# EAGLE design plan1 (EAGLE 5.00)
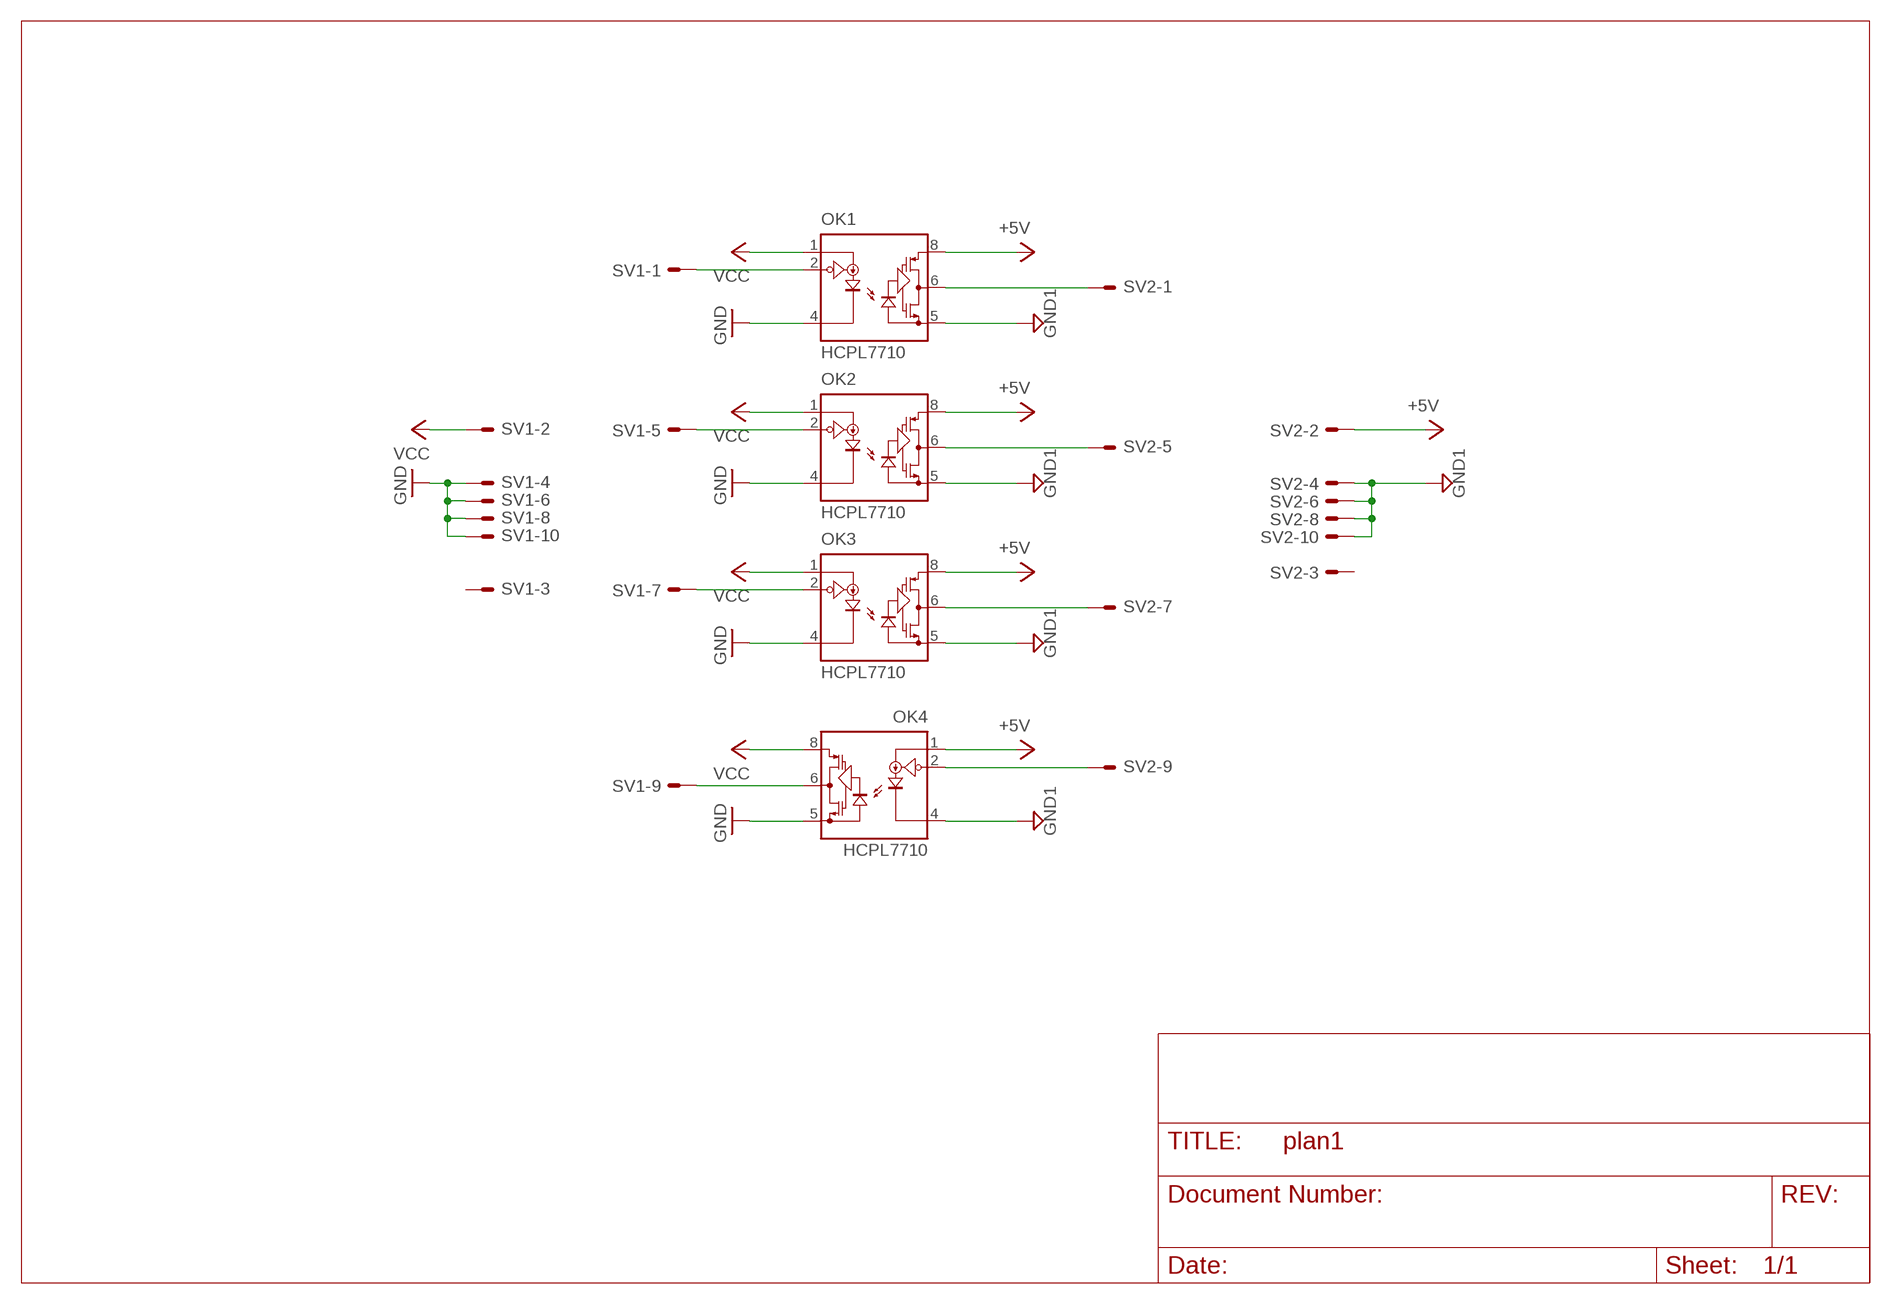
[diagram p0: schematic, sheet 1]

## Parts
OK1  HCPL7710  HCPL7720  [DIL08]
OK2  HCPL7710  HCPL7720  [DIL08]
OK3  HCPL7710  HCPL7720  [DIL08]
OK4  HCPL7710  HCPL7720  [DIL08]
SV1  ML10E  [ML10]
SV2  ML10E  [ML10]

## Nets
+5V: OK1.8(VDD2) OK2.8(VDD2) OK3.8(VDD2) OK4.1(VDD1) SV2.2
GND: OK1.4(GND1) OK2.4(GND1) OK3.4(GND1) OK4.5(GND2) SV1.4 SV1.6 SV1.8 SV1.10
GND1: OK1.5(GND2) OK2.5(GND2) OK3.5(GND2) OK4.4(GND1) SV2.4 SV2.6 SV2.8 SV2.10
N$1: OK1.2(VI) SV1.1
N$2: OK2.2(VI) SV1.5
N$3: OK3.2(VI) SV1.7
N$4: OK4.6(VO) SV1.9
N$5: OK1.6(VO) SV2.1
N$6: OK2.6(VO) SV2.5
N$7: OK3.6(VO) SV2.7
N$8: OK4.2(VI) SV2.9
VCC: OK1.1(VDD1) OK2.1(VDD1) OK3.1(VDD1) OK4.8(VDD2) SV1.2
Unconnected: SV1.3 SV2.3

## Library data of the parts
OK1-OK4 = optocoupler:HCPL772*: 40 ns Propagation Delay, CMOS Optocoupler *Pin 3 is the anode of the internal LED and must be left unconnected for guaranteed data sheet perfomance. Pin 7 is not connected internally. Source: HCPL7721.pdf
SV1 SV2 = con-harting-ml:ML10?E: HARTING

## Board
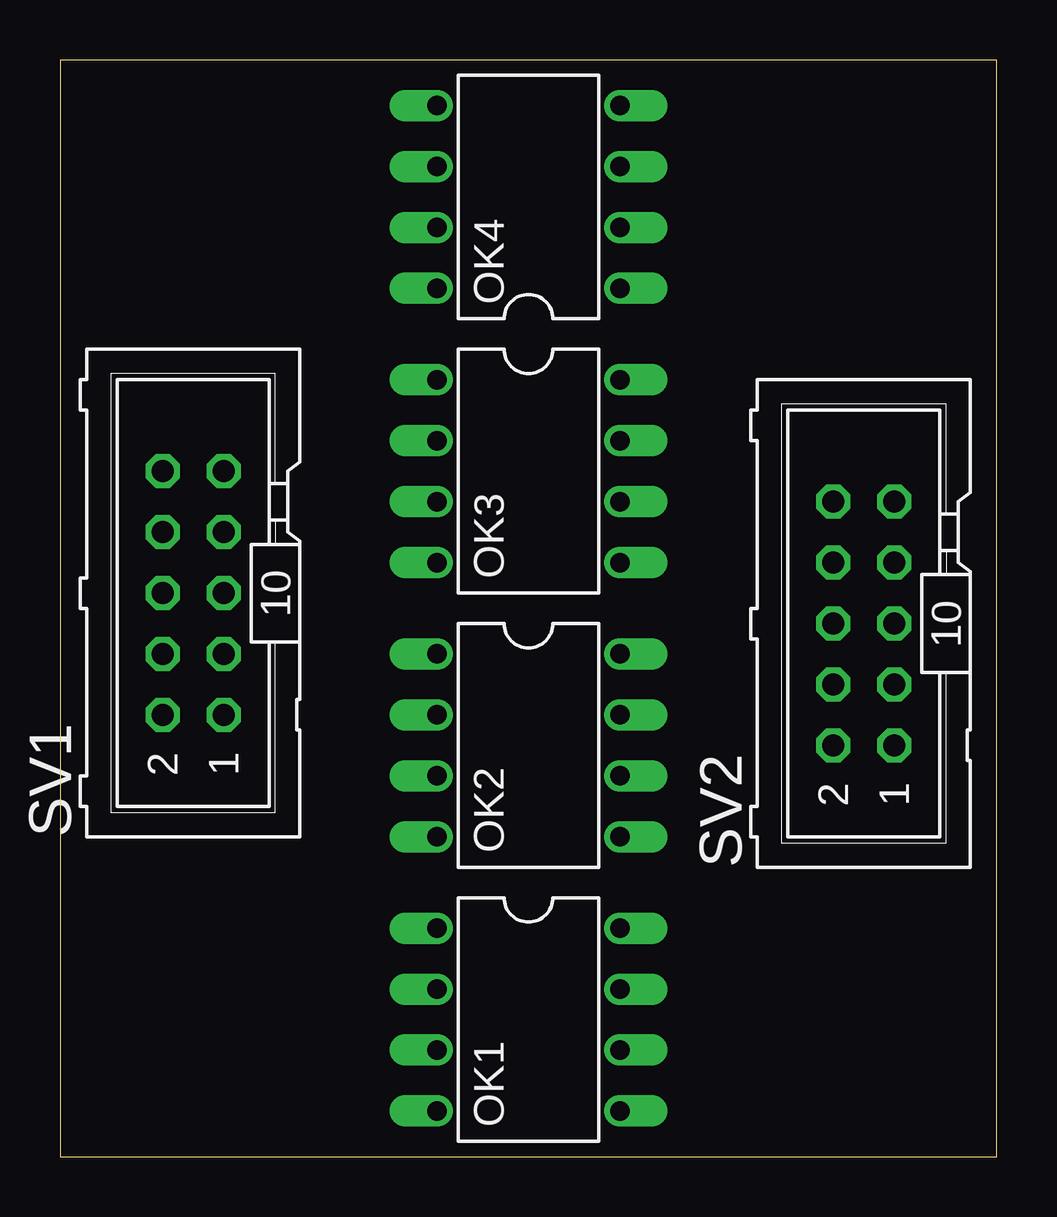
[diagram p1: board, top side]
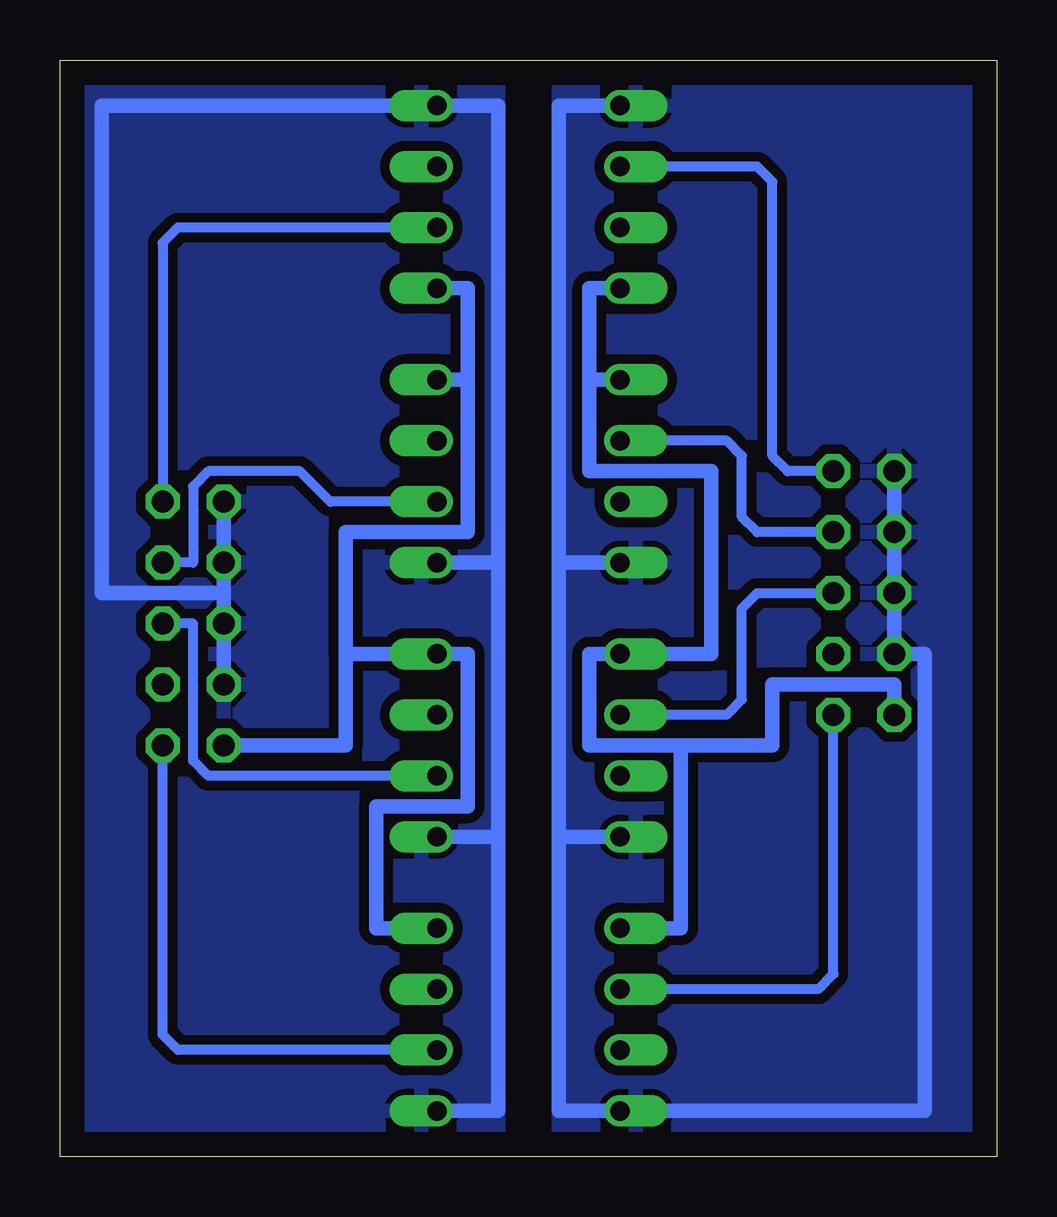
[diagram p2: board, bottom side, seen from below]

Size 39.04 x 45.71 mm. Coordinates in mm from the lower left corner, seen from the top.
Outline: 0,0 39.04,0 39.04,45.71 0,45.71 0,0
Copper layers (1*16): Top 0.035mm / dielectric 1.5mm / Bottom 0.035mm
Design rules "default": minimum track width 10mil, minimum drill 24mil, track to track 8mil, track to pad 8mil, pad to pad 8mil, via to via 8mil, smd to smd 8mil, copper to edge 40mil, drill to drill 8mil, minimum pad ring 10mil, minimum via ring 8mil, stop-mask expansion 4mil, vias tented up to drill 0mil, thermal gap 10mil

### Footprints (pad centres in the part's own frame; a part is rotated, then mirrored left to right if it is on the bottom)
DIL08 = drill 0.813 offset: 1 -3.81,-3.81; 2 -1.27,-3.81; 3 1.27,-3.81; 4 3.81,-3.81; 5 3.81,3.81; 6 1.27,3.81; 7 -1.27,3.81; 8 -3.81,3.81
ML10 = drill 0.914 octagon: 1 -5.08,-1.27; 2 -5.08,1.27; 3 -2.54,-1.27; 4 -2.54,1.27; 5 0,-1.27; 6 0,1.27; 7 2.54,-1.27; 8 2.54,1.27; 9 5.08,-1.27; 10 5.08,1.27

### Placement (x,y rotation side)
OK1  19.52,5.71 270 top
OK2  19.52,17.14 270 top
OK3  19.52,28.57 270 top
OK4  19.52,40 90 top
SV1  5.55,23.49 90 top
SV2  33.49,22.22 90 top

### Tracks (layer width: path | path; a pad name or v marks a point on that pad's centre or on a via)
+5V
  Bottom 0.61: OK1.8 25.87,9.52 25.87,14.6 22.06,14.6 22.06,20.95 OK2.8 27.14,20.95 | 27.14,20.95 27.14,17.14 SV2.2 | OK4.1 22.06,36.19 22.06,32.38 | 22.06,32.38 OK3.8 | 27.14,20.95 27.14,26.03 22.06,26.03 22.06,32.38
GND
  Bottom 0.61: SV1.10 SV1.8 4.28,24.76 | 4.28,24.76 SV1.6 SV1.4 | 18.25,13.33 OK2.4 | 18.25,13.33 18.25,24.76 | 18.25,24.76 OK3.4 | 18.25,13.33 18.25,1.9 OK1.4 3.01,1.9 3.01,20.95 SV1.4 | OK4.5 18.25,43.81 18.25,24.76 | SV1.4 4.28,24.76
  pour Bottom (isolate 0.406): 0.47,45.08 18.25,45.08 18.25,0.63 0.47,0.63
GND1
  Bottom 0.61: 20.79,13.33 OK2.5 | 20.79,13.33 20.79,24.76 | 20.79,24.76 OK3.5 | 20.79,24.76 20.79,43.81 OK4.4 37.3,43.81 37.3,23.49 32.22,23.49 SV2.8 | OK1.5 20.79,1.9 20.79,13.33 | SV2.4 SV2.6 SV2.8 | SV2.8 SV2.10
  pour Bottom (isolate 0.406): 38.57,45.08 20.79,45.08 20.79,0.63 38.57,0.63
N$1
  Bottom 0.406: SV1.1 6.82,7.62 7.46,6.98 OK1.2
N$2
  Bottom 0.406: OK2.2 11.27,18.41 10.63,19.05 10.63,22.86 10,23.49 SV1.5
N$3
  Bottom 0.406: SV1.7 10,26.03 10.63,26.66 10.63,29.2 11.27,29.84 OK3.2
N$4
  Bottom 0.406: SV1.9 8.72,28.57 9.36,29.2 9.36,40.63 10,41.27 OK4.6
N$5
  Bottom 0.406: OK1.6 34.12,4.44 34.76,5.08 SV2.1
N$6
  Bottom 0.406: OK2.6 32.86,15.87 33.49,16.5 33.49,22.22 SV2.5
N$7
  Bottom 0.406: OK3.6 27.77,27.3 28.41,27.93 29.04,28.57 32.86,28.57 33.49,27.93 33.49,24.76 SV2.7
N$8
  Bottom 0.406: OK4.2 34.12,38.73 34.76,38.09 SV2.9
VCC
  Bottom 0.61: SV1.2 4.28,19.68 9.36,19.68 9.36,17.14 13.17,17.14 | 13.17,17.14 16.98,17.14 16.98,20.95 OK2.1 11.9,20.95 11.9,28.57 16.98,28.57 16.98,32.38 | OK1.1 13.17,9.52 13.17,17.14 | OK4.8 16.98,36.19 16.98,32.38 | 16.98,32.38 OK3.1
